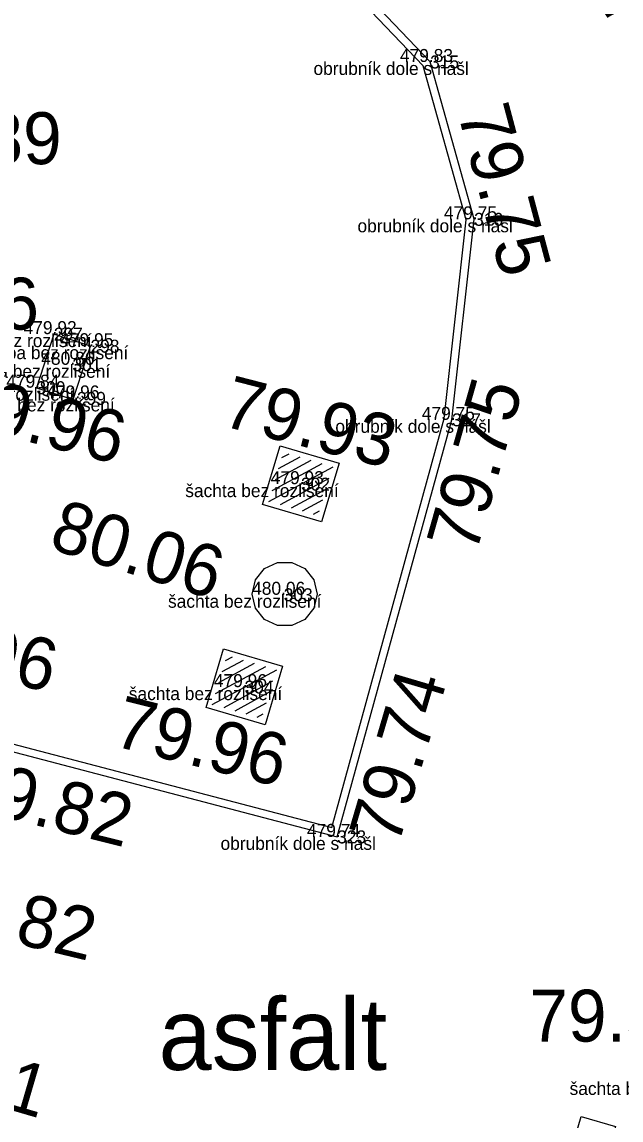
# Model space of a CAD drawing. Extents: x -888468 to -888310, y -1023047 to -1022832.
# Drawn here: x -888341.14 to -888331.91, y -1022875.57 to -1022858.65 of the extents above; entities that cross this region are included whole.
import ezdxf

# ---------------------------------------------------------------- set-up
doc = ezdxf.new("R2010")
doc.units = 0
for name, color, linetype in [('035-spod', 7, 'Continuous'), ('32 betonové patky', 7, 'Continuous'), ('4 obrubník dole', 7, 'Continuous'), ('52 šachta bez rozlišení', 7, 'Continuous'), ('55 uliční vpust', 7, 'Continuous'), ('80 šachta hranatá', 7, 'Continuous'), ('83 semafor', 7, 'Continuous'), ('bod', 7, 'Continuous'), ('bod kod', 7, 'Continuous'), ('bod výška', 7, 'Continuous'), ('bod číslo', 7, 'Continuous'), ('Nadmořská výška TISK', 7, 'Continuous'), ('popisy', 7, 'Continuous')]:
    doc.layers.add(name, color=color, linetype=linetype)

msp = doc.modelspace()

# ---------------------------------------------------------------- linework, layer by layer
at = {"layer": '035-spod'}
for p, q in [((-888334.854, -1022859.268), (-888334.854, -1022859.268)), ((-888334.854, -1022859.268), (-888334.854, -1022859.268)), ((-888334.854, -1022859.268), (-888334.854, -1022859.268)), ((-888334.854, -1022859.268), (-888334.854, -1022859.268)), ((-888334.176, -1022861.693), (-888334.176, -1022861.693)), ((-888334.176, -1022861.693), (-888334.176, -1022861.693)), ((-888334.176, -1022861.693), (-888334.176, -1022861.693)), ((-888334.176, -1022861.693), (-888334.176, -1022861.693)), ((-888340.651, -1022863.462), (-888340.651, -1022863.462)), ((-888340.651, -1022863.462), (-888340.651, -1022863.462)), ((-888340.651, -1022863.462), (-888340.651, -1022863.462)), ((-888340.651, -1022863.462), (-888340.651, -1022863.462)), ((-888340.086, -1022863.648), (-888340.086, -1022863.648)), ((-888340.086, -1022863.648), (-888340.086, -1022863.648)), ((-888340.086, -1022863.648), (-888340.086, -1022863.648)), ((-888340.086, -1022863.648), (-888340.086, -1022863.648)), ((-888340.365, -1022863.935), (-888340.365, -1022863.935)), ((-888340.365, -1022863.935), (-888340.365, -1022863.935)), ((-888340.365, -1022863.935), (-888340.365, -1022863.935)), ((-888340.365, -1022863.935), (-888340.365, -1022863.935)), ((-888340.919, -1022864.288), (-888340.919, -1022864.288)), ((-888340.919, -1022864.288), (-888340.919, -1022864.288)), ((-888340.919, -1022864.288), (-888340.919, -1022864.288)), ((-888340.919, -1022864.288), (-888340.919, -1022864.288)), ((-888340.295, -1022864.453), (-888340.295, -1022864.453)), ((-888340.295, -1022864.453), (-888340.295, -1022864.453)), ((-888340.295, -1022864.453), (-888340.295, -1022864.453)), ((-888340.295, -1022864.453), (-888340.295, -1022864.453)), ((-888334.517, -1022864.783), (-888334.517, -1022864.783)), ((-888334.517, -1022864.783), (-888334.517, -1022864.783)), ((-888334.517, -1022864.783), (-888334.517, -1022864.783)), ((-888334.517, -1022864.783), (-888334.517, -1022864.783)), ((-888336.843, -1022865.774), (-888336.843, -1022865.774)), ((-888336.843, -1022865.774), (-888336.843, -1022865.774)), ((-888336.843, -1022865.774), (-888336.843, -1022865.774)), ((-888336.843, -1022865.774), (-888336.843, -1022865.774)), ((-888337.109, -1022867.479), (-888337.109, -1022867.479)), ((-888337.109, -1022867.479), (-888337.109, -1022867.479)), ((-888337.109, -1022867.479), (-888337.109, -1022867.479)), ((-888337.109, -1022867.479), (-888337.109, -1022867.479)), ((-888337.713, -1022868.902), (-888337.713, -1022868.902)), ((-888337.713, -1022868.902), (-888337.713, -1022868.902)), ((-888337.713, -1022868.902), (-888337.713, -1022868.902)), ((-888337.713, -1022868.902), (-888337.713, -1022868.902)), ((-888336.286, -1022871.21), (-888336.286, -1022871.21)), ((-888336.286, -1022871.21), (-888336.286, -1022871.21)), ((-888336.286, -1022871.21), (-888336.286, -1022871.21)), ((-888336.286, -1022871.21), (-888336.286, -1022871.21))]:
    msp.add_line(p, q, dxfattribs=at)
at = {"layer": '32 betonové patky'}
msp.add_lwpolyline([(-888340.651, -1022863.462), (-888340.919, -1022864.288), (-888340.353, -1022864.472), (-888340.085, -1022863.646)], close=True, dxfattribs=at)
at = {"layer": '4 obrubník dole'}
for points in [[(-888341.752, -1022869.778), (-888336.286, -1022871.21), (-888334.517, -1022864.783), (-888334.176, -1022861.693), (-888334.854, -1022859.268), (-888337.294, -1022856.707), (-888339.481, -1022855.175), (-888342.875, -1022853.816), (-888345.02, -1022853.306), (-888348.237, -1022852.954), (-888351.921, -1022852.764), (-888355.066, -1022852.699), (-888361.16, -1022852.766)], [(-888341.722, -1022869.662), (-888336.37, -1022871.064), (-888334.635, -1022864.76), (-888334.298, -1022861.703), (-888334.962, -1022859.329), (-888337.373, -1022856.798), (-888339.538, -1022855.281), (-888342.911, -1022853.931), (-888345.04, -1022853.424), (-888348.247, -1022853.074), (-888351.925, -1022852.884), (-888355.067, -1022852.819), (-888361.149, -1022852.886)]]:
    msp.add_lwpolyline(points, dxfattribs=at)
at = {"layer": '52 šachta bez rozlišení'}
for p, q in [((-888337.406, -1022867.076), (-888337.205, -1022866.979)), ((-888337.205, -1022866.979), (-888336.982, -1022866.979)), ((-888336.982, -1022866.979), (-888336.782, -1022867.076)), ((-888337.544, -1022867.25), (-888337.406, -1022867.076)), ((-888336.782, -1022867.076), (-888336.643, -1022867.25)), ((-888337.594, -1022867.467), (-888337.544, -1022867.25)), ((-888336.643, -1022867.25), (-888336.594, -1022867.467)), ((-888337.544, -1022867.684), (-888337.594, -1022867.467)), ((-888336.594, -1022867.467), (-888336.643, -1022867.684)), ((-888337.406, -1022867.858), (-888337.544, -1022867.684)), ((-888336.643, -1022867.684), (-888336.782, -1022867.858)), ((-888337.205, -1022867.954), (-888337.406, -1022867.858)), ((-888336.982, -1022867.954), (-888337.205, -1022867.954)), ((-888336.782, -1022867.858), (-888336.982, -1022867.954))]:
    msp.add_line(p, q, dxfattribs=at)
at = {"layer": '55 uliční vpust'}
msp.add_lwpolyline([(-888332.073, -1022875.937), (-888332.15, -1022876.201), (-888332.678, -1022876.047), (-888332.524, -1022875.519), (-888331.996, -1022875.673), (-888332.073, -1022875.937), (-888332.601, -1022875.783)], dxfattribs=at)
at = {"layer": '80 šachta hranatá'}
for p, q in [((-888337.435, -1022866.087), (-888337.165, -1022865.182)), ((-888337.165, -1022865.182), (-888336.257, -1022865.45)), ((-888337.289, -1022865.873), (-888336.517, -1022865.456)), ((-888337.238, -1022865.704), (-888336.686, -1022865.406)), ((-888337.188, -1022865.535), (-888336.856, -1022865.355)), ((-888337.137, -1022865.365), (-888337.027, -1022865.306)), ((-888336.257, -1022865.45), (-888336.525, -1022866.357)), ((-888337.339, -1022866.042), (-888336.347, -1022865.506)), ((-888337.159, -1022866.087), (-888336.407, -1022865.68)), ((-888336.99, -1022866.137), (-888336.457, -1022865.849)), ((-888336.525, -1022866.357), (-888337.435, -1022866.087)), ((-888336.82, -1022866.187), (-888336.507, -1022866.018)), ((-888336.651, -1022866.238), (-888336.557, -1022866.187)), ((-888338.304, -1022869.216), (-888338.036, -1022868.311)), ((-888338.036, -1022868.311), (-888337.127, -1022868.577)), ((-888338.058, -1022868.663), (-888337.727, -1022868.484)), ((-888338.008, -1022868.494), (-888337.898, -1022868.434)), ((-888338.209, -1022869.171), (-888337.217, -1022868.633)), ((-888338.158, -1022869.002), (-888337.387, -1022868.583)), ((-888338.108, -1022868.833), (-888337.557, -1022868.533)), ((-888337.127, -1022868.577), (-888337.394, -1022869.485)), ((-888338.028, -1022869.215), (-888337.277, -1022868.807)), ((-888337.859, -1022869.265), (-888337.327, -1022868.977)), ((-888337.69, -1022869.315), (-888337.377, -1022869.146)), ((-888337.394, -1022869.485), (-888338.304, -1022869.216)), ((-888337.52, -1022869.365), (-888337.426, -1022869.315))]:
    msp.add_line(p, q, dxfattribs=at)
at = {"layer": '83 semafor'}
for p, q in [((-888334.854, -1022859.268), (-888334.854, -1022859.268)), ((-888334.176, -1022861.693), (-888334.176, -1022861.693)), ((-888340.651, -1022863.462), (-888340.651, -1022863.462)), ((-888340.086, -1022863.648), (-888340.086, -1022863.648)), ((-888340.365, -1022863.935), (-888340.365, -1022863.935)), ((-888340.919, -1022864.288), (-888340.919, -1022864.288)), ((-888340.295, -1022864.453), (-888340.295, -1022864.453)), ((-888334.517, -1022864.783), (-888334.517, -1022864.783)), ((-888336.843, -1022865.774), (-888336.843, -1022865.774)), ((-888337.109, -1022867.479), (-888337.109, -1022867.479)), ((-888337.713, -1022868.902), (-888337.713, -1022868.902)), ((-888336.286, -1022871.21), (-888336.286, -1022871.21))]:
    msp.add_line(p, q, dxfattribs=at)
at = {"layer": 'bod'}
for p, q in [((-888334.854, -1022859.268), (-888334.854, -1022859.268)), ((-888334.176, -1022861.693), (-888334.176, -1022861.693)), ((-888340.651, -1022863.462), (-888340.651, -1022863.462)), ((-888340.086, -1022863.648), (-888340.086, -1022863.648)), ((-888340.365, -1022863.935), (-888340.365, -1022863.935)), ((-888340.919, -1022864.288), (-888340.919, -1022864.288)), ((-888340.295, -1022864.453), (-888340.295, -1022864.453)), ((-888334.517, -1022864.783), (-888334.517, -1022864.783)), ((-888336.843, -1022865.774), (-888336.843, -1022865.774)), ((-888337.109, -1022867.479), (-888337.109, -1022867.479)), ((-888337.713, -1022868.902), (-888337.713, -1022868.902)), ((-888336.286, -1022871.21), (-888336.286, -1022871.21))]:
    msp.add_line(p, q, dxfattribs=at)

# ---------------------------------------------------------------- texts
at = {"layer": 'bod kod'}
for s, p in [('obrubník dole s nášl', (-888336.651, -1022859.468)), ('obrubník dole s nášl', (-888335.973, -1022861.893)), ('stavba bez rozlišení', (-888342.432, -1022863.662)), ('stavba bez rozlišení', (-888341.867, -1022863.848)), ('stavba bez rozlišení', (-888342.146, -1022864.135)), ('stavba bez rozlišení', (-888342.7, -1022864.488)), ('stavba bez rozlišení', (-888342.076, -1022864.653)), ('obrubník dole s nášl', (-888336.314, -1022864.983)), ('šachta bez rozlišení', (-888338.626, -1022865.974)), ('šachta bez rozlišení', (-888338.892, -1022867.679)), ('šachta bez rozlišení', (-888339.496, -1022869.102)), ('obrubník dole s nášl', (-888338.083, -1022871.41)), ('šachta bez rozlišení', (-888332.705, -1022875.187))]:
    msp.add_text(s, height=0.2, dxfattribs=at).set_placement(p)
at = {"layer": 'bod výška'}
for s, p in [('479.83', (-888335.319, -1022859.268)), ('479.75', (-888334.641, -1022861.693)), ('479.92', (-888341.117, -1022863.462)), ('479.95', (-888340.552, -1022863.648)), ('480.86', (-888340.844, -1022863.935)), ('479.84', (-888341.384, -1022864.288)), ('479.96', (-888340.767, -1022864.453)), ('479.75', (-888334.982, -1022864.783)), ('479.93', (-888337.309, -1022865.774)), ('480.06', (-888337.596, -1022867.479)), ('479.96', (-888338.185, -1022868.902)), ('479.74', (-888336.751, -1022871.21))]:
    msp.add_text(s, height=0.2, dxfattribs=at).set_placement(p)
at = {"layer": 'bod číslo'}
for s, p in [('315', (-888334.854, -1022859.368)), ('316', (-888334.176, -1022861.793)), ('297', (-888340.651, -1022863.562)), ('298', (-888340.086, -1022863.748)), ('301', (-888340.365, -1022864.035)), ('300', (-888340.919, -1022864.388)), ('299', (-888340.295, -1022864.553)), ('317', (-888334.517, -1022864.883)), ('302', (-888336.843, -1022865.874)), ('303', (-888337.109, -1022867.579)), ('304', (-888337.713, -1022869.002)), ('323', (-888336.286, -1022871.31))]:
    msp.add_text(s, height=0.2, dxfattribs=at).set_placement(p)
at = {"layer": 'Nadmořská výška TISK'}
for s, rotation, p in [('79.74', 303.182, (-888333.093, -1022857.102)), ('79.75', 284.9134, (-888334.434, -1022860.04)), ('79.96', 345.7861, (-888342.264, -1022864.814)), ('79.93', 345.6011, (-888338.092, -1022864.867)), ('79.75', 74.176, (-888334.149, -1022866.868)), ('80.06', 342.6485, (-888340.751, -1022866.757)), ('79.96', 346.5027, (-888343.318, -1022868.362)), ('79.74', 73.5282, (-888335.347, -1022871.365)), ('79.96', 346.0514, (-888339.766, -1022869.8)), ('79.82', 346.0398, (-888342.158, -1022870.726)), ('79.82', 346.471, (-888342.718, -1022872.496)), ('79.81', 343.6864, (-888343.443, -1022874.797))]:
    msp.add_text(s, height=0.8, rotation=rotation, dxfattribs=at).set_placement(p)
for s, p in [('79.89', (-888343.207, -1022860.843)), ('79.66', (-888343.557, -1022863.392)), ('79.57', (-888333.325, -1022874.365))]:
    msp.add_text(s, height=0.8, dxfattribs=at).set_placement(p)
at = {"layer": 'popisy'}
msp.add_text('asfalt', height=1.1016, dxfattribs=at).set_placement((-888339.037, -1022874.801))

doc.saveas('drawing.dxf')
